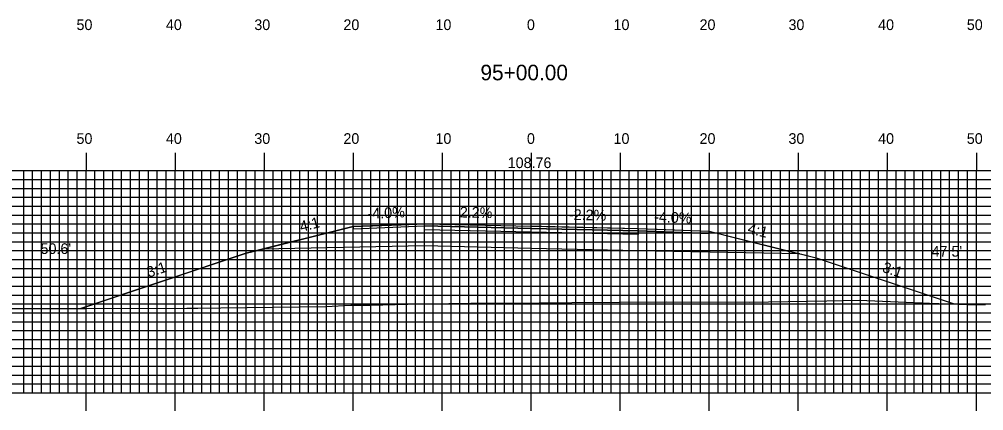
# Model space of a CAD drawing. Extents: x 1765333 to 1765676, y 442591 to 442811.
# Drawn here: x 1765440.9 to 1765549.2, y 442696.7 to 442740.7 of the extents above; entities that cross this region are included whole.
import ezdxf

# ---------------------------------------------------------------- set-up
doc = ezdxf.new("R2010")
doc.units = 0
for name, color, linetype in [('ANNOTATION', 7, 'Continuous'), ('D_Roadway_Centerline', 7, 'Continuous'), ('D_Roadway_Centerline_Text', 7, 'Continuous'), ('D_Roadway_Edge_Shoulder', 7, 'Continuous'), ('D_Roadway_Edge_TW', 7, 'Continuous'), ('D_Roadway_Pavement', 7, 'Continuous'), ('D_Roadway_SlopeLines', 7, 'Continuous'), ('D_Roadway_SubGrade', 7, 'Continuous'), ('D_Text_Standard', 7, 'Continuous'), ('H_V ANNOTATION', 7, 'Continuous'), ('MAJOR', 7, 'Continuous'), ('MINOR', 7, 'Continuous'), ('S_Roadway_Centerline', 7, 'Continuous')]:
    doc.layers.add(name, color=color, linetype=linetype)

msp = doc.modelspace()

# ---------------------------------------------------------------- linework, layer by layer
at = {"layer": 'D_Roadway_Centerline'}
msp.add_lwpolyline([(1765447.77, 442708.17), (1765451.1, 442709.28), (1765466.36, 442714.37), (1765466.37, 442714.37), (1765467.78, 442714.72), (1765468.2, 442714.83), (1765469.65, 442715.19), (1765478.37, 442717.37), (1765478.38, 442717.37), (1765483.77, 442717.58), (1765486.37, 442717.69), (1765486.37, 442717.69), (1765498.37, 442717.42), (1765499.53, 442717.4), (1765510.37, 442717.16), (1765512.51, 442717.07), (1765518.37, 442716.84), (1765518.37, 442716.84), (1765527.84, 442714.47), (1765528.54, 442714.3), (1765528.75, 442714.25), (1765530.37, 442713.84), (1765545.86, 442708.68), (1765545.86, 442708.68)], dxfattribs=at)
at = {"layer": 'D_Roadway_Edge_Shoulder'}
for points in [[(1765486.37, 442717.69), (1765478.37, 442717.37), (1765478.37, 442717.12), (1765486.37, 442717.44)], [(1765510.37, 442717.16), (1765518.37, 442716.84), (1765518.37, 442716.59), (1765510.37, 442716.91)]]:
    msp.add_lwpolyline(points, close=True, dxfattribs=at)
at = {"layer": 'D_Roadway_Edge_TW'}
msp.add_lwpolyline([(1765486.37, 442717.44), (1765486.37, 442717.69), (1765498.37, 442717.42), (1765510.37, 442717.16), (1765510.37, 442716.91), (1765498.37, 442717.17)], close=True, dxfattribs=at)
at = {"layer": 'D_Roadway_Pavement'}
msp.add_lwpolyline([(1765486.37, 442717.02), (1765486.37, 442717.44), (1765498.37, 442717.17), (1765510.37, 442716.91), (1765510.37, 442716.49), (1765498.37, 442716.76)], close=True, dxfattribs=at)
at = {"layer": 'D_Roadway_SlopeLines'}
for points in [[(1765478.37, 442717.37), (1765466.37, 442714.37), (1765447.77, 442708.17)], [(1765518.37, 442716.84), (1765530.37, 442713.84), (1765545.86, 442708.68)]]:
    msp.add_lwpolyline(points, dxfattribs=at)
at = {"layer": 'D_Roadway_SubGrade'}
msp.add_lwpolyline([(1765486.37, 442715.19), (1765468.2, 442714.83), (1765478.37, 442717.37), (1765478.37, 442717.12), (1765486.37, 442717.44), (1765498.37, 442717.17), (1765510.37, 442716.91), (1765518.37, 442716.59), (1765518.37, 442716.84), (1765528.54, 442714.3), (1765510.37, 442714.66), (1765498.37, 442714.92)], close=True, dxfattribs=at)
at = {"layer": 'MAJOR'}
for p, q in [((1765448.37, 442725.67), (1765448.37, 442723.67)), ((1765458.37, 442725.67), (1765458.37, 442723.67)), ((1765468.37, 442725.67), (1765468.37, 442723.67)), ((1765478.37, 442725.67), (1765478.37, 442723.67)), ((1765488.37, 442725.67), (1765488.37, 442723.67)), ((1765498.37, 442725.67), (1765498.37, 442723.67)), ((1765508.37, 442725.67), (1765508.37, 442723.67)), ((1765518.37, 442725.67), (1765518.37, 442723.67)), ((1765528.37, 442725.67), (1765528.37, 442723.67)), ((1765538.37, 442725.67), (1765538.37, 442723.67)), ((1765548.37, 442725.67), (1765548.37, 442723.67)), ((1765358.37, 442723.67), (1765638.37, 442723.67)), ((1765358.37, 442723.67), (1765638.37, 442723.67)), ((1765448.37, 442698.67), (1765448.37, 442723.67)), ((1765458.37, 442698.67), (1765458.37, 442723.67)), ((1765468.37, 442698.67), (1765468.37, 442723.67)), ((1765478.37, 442698.67), (1765478.37, 442723.67)), ((1765488.37, 442698.67), (1765488.37, 442723.67)), ((1765498.37, 442698.67), (1765498.37, 442723.67)), ((1765508.37, 442698.67), (1765508.37, 442723.67)), ((1765518.37, 442698.67), (1765518.37, 442723.67)), ((1765528.37, 442698.67), (1765528.37, 442723.67)), ((1765538.37, 442698.67), (1765538.37, 442723.67)), ((1765548.37, 442698.67), (1765548.37, 442723.67)), ((1765358.37, 442718.67), (1765638.37, 442718.67)), ((1765358.37, 442713.67), (1765638.37, 442713.67)), ((1765358.37, 442708.67), (1765638.37, 442708.67)), ((1765358.37, 442703.67), (1765638.37, 442703.67)), ((1765358.37, 442698.67), (1765638.37, 442698.67)), ((1765358.37, 442698.67), (1765638.37, 442698.67)), ((1765448.37, 442696.66), (1765448.37, 442698.67)), ((1765458.37, 442696.66), (1765458.37, 442698.67)), ((1765468.37, 442696.66), (1765468.37, 442698.67)), ((1765478.37, 442696.66), (1765478.37, 442698.67)), ((1765488.37, 442696.66), (1765488.37, 442698.67)), ((1765498.37, 442696.66), (1765498.37, 442698.67)), ((1765508.37, 442696.66), (1765508.37, 442698.67)), ((1765518.37, 442696.66), (1765518.37, 442698.67)), ((1765528.37, 442696.66), (1765528.37, 442698.67)), ((1765538.37, 442696.66), (1765538.37, 442698.67)), ((1765548.37, 442696.66), (1765548.37, 442698.67))]:
    msp.add_line(p, q, dxfattribs=at)
at = {"layer": 'MINOR'}
for p, q in [((1765441.37, 442698.67), (1765441.37, 442723.67)), ((1765442.37, 442698.67), (1765442.37, 442723.67)), ((1765443.37, 442698.67), (1765443.37, 442723.67)), ((1765444.37, 442698.67), (1765444.37, 442723.67)), ((1765445.37, 442698.67), (1765445.37, 442723.67)), ((1765446.37, 442698.67), (1765446.37, 442723.67)), ((1765447.37, 442698.67), (1765447.37, 442723.67)), ((1765449.37, 442698.67), (1765449.37, 442723.67)), ((1765450.37, 442698.67), (1765450.37, 442723.67)), ((1765451.37, 442698.67), (1765451.37, 442723.67)), ((1765452.37, 442698.67), (1765452.37, 442723.67)), ((1765453.37, 442698.67), (1765453.37, 442723.67)), ((1765454.37, 442698.67), (1765454.37, 442723.67)), ((1765455.37, 442698.67), (1765455.37, 442723.67)), ((1765456.37, 442698.67), (1765456.37, 442723.67)), ((1765457.37, 442698.67), (1765457.37, 442723.67)), ((1765459.37, 442698.67), (1765459.37, 442723.67)), ((1765460.37, 442698.67), (1765460.37, 442723.67)), ((1765461.37, 442698.67), (1765461.37, 442723.67)), ((1765462.37, 442698.67), (1765462.37, 442723.67)), ((1765463.37, 442698.67), (1765463.37, 442723.67)), ((1765464.37, 442698.67), (1765464.37, 442723.67)), ((1765465.37, 442698.67), (1765465.37, 442723.67)), ((1765466.37, 442698.67), (1765466.37, 442723.67)), ((1765467.37, 442698.67), (1765467.37, 442723.67)), ((1765469.37, 442698.67), (1765469.37, 442723.67)), ((1765470.37, 442698.67), (1765470.37, 442723.67)), ((1765471.37, 442698.67), (1765471.37, 442723.67)), ((1765472.37, 442698.67), (1765472.37, 442723.67)), ((1765473.37, 442698.67), (1765473.37, 442723.67)), ((1765474.37, 442698.67), (1765474.37, 442723.67)), ((1765475.37, 442698.67), (1765475.37, 442723.67)), ((1765476.37, 442698.67), (1765476.37, 442723.67)), ((1765477.37, 442698.67), (1765477.37, 442723.67)), ((1765479.37, 442698.67), (1765479.37, 442723.67)), ((1765480.37, 442698.67), (1765480.37, 442723.67)), ((1765481.37, 442698.67), (1765481.37, 442723.67)), ((1765482.37, 442698.67), (1765482.37, 442723.67)), ((1765483.37, 442698.67), (1765483.37, 442723.67)), ((1765484.37, 442698.67), (1765484.37, 442723.67)), ((1765485.37, 442698.67), (1765485.37, 442723.67)), ((1765486.37, 442698.67), (1765486.37, 442723.67)), ((1765487.37, 442698.67), (1765487.37, 442723.67)), ((1765489.37, 442698.67), (1765489.37, 442723.67)), ((1765490.37, 442698.67), (1765490.37, 442723.67)), ((1765491.37, 442698.67), (1765491.37, 442723.67)), ((1765492.37, 442698.67), (1765492.37, 442723.67)), ((1765493.37, 442698.67), (1765493.37, 442723.67)), ((1765494.37, 442698.67), (1765494.37, 442723.67)), ((1765495.37, 442698.67), (1765495.37, 442723.67)), ((1765496.37, 442698.67), (1765496.37, 442723.67)), ((1765497.37, 442698.67), (1765497.37, 442723.67)), ((1765499.37, 442698.67), (1765499.37, 442723.67)), ((1765500.37, 442698.67), (1765500.37, 442723.67)), ((1765501.37, 442698.67), (1765501.37, 442723.67)), ((1765502.37, 442698.67), (1765502.37, 442723.67)), ((1765503.37, 442698.67), (1765503.37, 442723.67)), ((1765504.37, 442698.67), (1765504.37, 442723.67)), ((1765505.37, 442698.67), (1765505.37, 442723.67)), ((1765506.37, 442698.67), (1765506.37, 442723.67)), ((1765507.37, 442698.67), (1765507.37, 442723.67)), ((1765509.37, 442698.67), (1765509.37, 442723.67)), ((1765510.37, 442698.67), (1765510.37, 442723.67)), ((1765511.37, 442698.67), (1765511.37, 442723.67)), ((1765512.37, 442698.67), (1765512.37, 442723.67)), ((1765513.37, 442698.67), (1765513.37, 442723.67)), ((1765514.37, 442698.67), (1765514.37, 442723.67)), ((1765515.37, 442698.67), (1765515.37, 442723.67)), ((1765516.37, 442698.67), (1765516.37, 442723.67)), ((1765517.37, 442698.67), (1765517.37, 442723.67)), ((1765519.37, 442698.67), (1765519.37, 442723.67)), ((1765520.37, 442698.67), (1765520.37, 442723.67)), ((1765521.37, 442698.67), (1765521.37, 442723.67)), ((1765522.37, 442698.67), (1765522.37, 442723.67)), ((1765523.37, 442698.67), (1765523.37, 442723.67)), ((1765524.37, 442698.67), (1765524.37, 442723.67)), ((1765525.37, 442698.67), (1765525.37, 442723.67)), ((1765526.37, 442698.67), (1765526.37, 442723.67)), ((1765527.37, 442698.67), (1765527.37, 442723.67)), ((1765529.37, 442698.67), (1765529.37, 442723.67)), ((1765530.37, 442698.67), (1765530.37, 442723.67)), ((1765531.37, 442698.67), (1765531.37, 442723.67)), ((1765532.37, 442698.67), (1765532.37, 442723.67)), ((1765533.37, 442698.67), (1765533.37, 442723.67)), ((1765534.37, 442698.67), (1765534.37, 442723.67)), ((1765535.37, 442698.67), (1765535.37, 442723.67)), ((1765536.37, 442698.67), (1765536.37, 442723.67)), ((1765537.37, 442698.67), (1765537.37, 442723.67)), ((1765539.37, 442698.67), (1765539.37, 442723.67)), ((1765540.37, 442698.67), (1765540.37, 442723.67)), ((1765541.37, 442698.67), (1765541.37, 442723.67)), ((1765542.37, 442698.67), (1765542.37, 442723.67)), ((1765543.37, 442698.67), (1765543.37, 442723.67)), ((1765544.37, 442698.67), (1765544.37, 442723.67)), ((1765545.37, 442698.67), (1765545.37, 442723.67)), ((1765546.37, 442698.67), (1765546.37, 442723.67)), ((1765547.37, 442698.67), (1765547.37, 442723.67)), ((1765358.37, 442722.67), (1765638.37, 442722.67)), ((1765358.37, 442721.67), (1765638.37, 442721.67)), ((1765358.37, 442720.67), (1765638.37, 442720.67)), ((1765358.37, 442719.67), (1765638.37, 442719.67)), ((1765358.37, 442717.67), (1765638.37, 442717.67)), ((1765358.37, 442716.67), (1765638.37, 442716.67)), ((1765358.37, 442715.67), (1765638.37, 442715.67)), ((1765358.37, 442714.67), (1765638.37, 442714.67)), ((1765358.37, 442712.67), (1765638.37, 442712.67)), ((1765358.37, 442711.67), (1765638.37, 442711.67)), ((1765358.37, 442710.67), (1765638.37, 442710.67)), ((1765358.37, 442709.67), (1765638.37, 442709.67)), ((1765358.37, 442707.67), (1765638.37, 442707.67)), ((1765358.37, 442706.67), (1765638.37, 442706.67)), ((1765358.37, 442705.67), (1765638.37, 442705.67)), ((1765358.37, 442704.67), (1765638.37, 442704.67)), ((1765358.37, 442702.67), (1765638.37, 442702.67)), ((1765358.37, 442701.67), (1765638.37, 442701.67)), ((1765358.37, 442700.67), (1765638.37, 442700.67)), ((1765358.37, 442699.67), (1765638.37, 442699.67))]:
    msp.add_line(p, q, dxfattribs=at)
at = {"layer": 'S_Roadway_Centerline'}
msp.add_lwpolyline([(1765423.88, 442708.16), (1765441.62, 442708.15), (1765448.42, 442708.17), (1765459.7, 442708.2), (1765460.94, 442708.21), (1765463.51, 442708.24), (1765475.31, 442708.38), (1765478.12, 442708.54), (1765480.27, 442708.54), (1765485.93, 442708.68), (1765486.61, 442708.69), (1765491.58, 442708.74), (1765495.6, 442708.75), (1765502.94, 442708.82), (1765513.58, 442708.9), (1765522.86, 442708.87), (1765531.57, 442709.01), (1765535.2, 442709.08), (1765543.11, 442708.77), (1765547.39, 442708.62), (1765549.41, 442708.6)], dxfattribs=at)

# ---------------------------------------------------------------- texts
at = {"layer": 'ANNOTATION'}
for s, rotation, p in [('-4.0%', 2.2905, (1765480.01, 442718.24)), ('2.2%', 358.7397, (1765490.34, 442718.4)), ('-2.2%', 358.7397, (1765502.6, 442718.13)), ('-4.0%', 357.7094, (1765512.16, 442717.89)), ('4:1', 14.0339, (1765472.54, 442716.77)), ('4:1', 345.9661, (1765522.61, 442716.64)), ('3:1', 18.4338, (1765455.41, 442711.62)), ('3:1', 341.5674, (1765537.72, 442712.3))]:
    msp.add_text(s, height=1.2, rotation=rotation, dxfattribs=at).set_placement(p)
at = {"layer": 'D_Roadway_Centerline'}
for s in ['C', 'L']:
    msp.add_text(s, height=0.0146, dxfattribs=at).set_placement((1765498.37, 442717.42))
at = {"layer": 'D_Roadway_Centerline_Text'}
msp.add_text('108.76', height=1.2, dxfattribs=at).set_placement((1765495.73, 442723.95))
at = {"layer": 'D_Text_Standard'}
for s, p in [("50.6'", (1765443.26, 442714.29)), ("47.5'", (1765543.34, 442713.99))]:
    msp.add_text(s, height=1.2, dxfattribs=at).set_placement(p)
at = {"layer": 'H_V ANNOTATION'}
for s, height, p in [('50', 1.2, (1765447.3, 442739.47)), ('40', 1.2, (1765457.34, 442739.47)), ('30', 1.2, (1765467.27, 442739.47)), ('20', 1.2, (1765477.28, 442739.47)), ('10', 1.2, (1765487.62, 442739.47)), ('0', 1.2, (1765497.89, 442739.47)), ('10', 1.2, (1765507.62, 442739.47)), ('20', 1.2, (1765517.28, 442739.47)), ('30', 1.2, (1765527.27, 442739.47)), ('40', 1.2, (1765537.34, 442739.47)), ('50', 1.2, (1765547.3, 442739.47)), ('95+00.00', 1.75, (1765492.67, 442733.82)), ('50', 1.2, (1765447.3, 442726.67)), ('40', 1.2, (1765457.34, 442726.67)), ('30', 1.2, (1765467.27, 442726.67)), ('20', 1.2, (1765477.28, 442726.67)), ('10', 1.2, (1765487.62, 442726.67)), ('0', 1.2, (1765497.89, 442726.67)), ('10', 1.2, (1765507.62, 442726.67)), ('20', 1.2, (1765517.28, 442726.67)), ('30', 1.2, (1765527.27, 442726.67)), ('40', 1.2, (1765537.34, 442726.67)), ('50', 1.2, (1765547.3, 442726.67))]:
    msp.add_text(s, height=height, dxfattribs=at).set_placement(p)

doc.saveas('drawing.dxf')
